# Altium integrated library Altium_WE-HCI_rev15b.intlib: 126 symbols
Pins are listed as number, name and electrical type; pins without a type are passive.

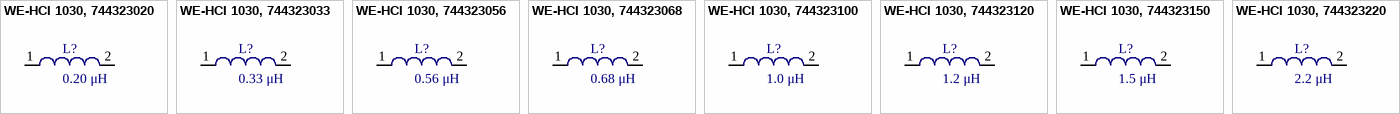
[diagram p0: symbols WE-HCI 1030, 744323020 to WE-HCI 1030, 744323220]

## WE-HCI 1030, 744323020
designator L?, comment 0.20 μH
WE-HCI SMD Flat Wire High Current Inductor, Inductance = 0.20 μH; partNo: 744323020; Manufacturer: Wurth Elektronik
footprint WE-HCI 1030
pins: 1, 2

## WE-HCI 1030, 744323033
designator L?, comment 0.33 μH
WE-HCI SMD Flat Wire High Current Inductor, Inductance = 0.33 μH; partNo: 744323033; Manufacturer: Wurth Elektronik
footprint WE-HCI 1030
pins: 1, 2

## WE-HCI 1030, 744323056
designator L?, comment 0.56 μH
WE-HCI SMD Flat Wire High Current Inductor, Inductance = 0.56 μH; partNo: 744323056; Manufacturer: Wurth Elektronik
footprint WE-HCI 1030
pins: 1, 2

## WE-HCI 1030, 744323068
designator L?, comment 0.68 μH
WE-HCI SMD Flat Wire High Current Inductor, Inductance = 0.68 μH; partNo: 744323068; Manufacturer: Wurth Elektronik
footprint WE-HCI 1030
pins: 1, 2

## WE-HCI 1030, 744323100
designator L?, comment 1.0 μH
WE-HCI SMD Flat Wire High Current Inductor, Inductance = 1.0 μH; partNo: 744323100; Manufacturer: Wurth Elektronik
footprint WE-HCI 1030
pins: 1, 2

## WE-HCI 1030, 744323120
designator L?, comment 1.2 μH
WE-HCI SMD Flat Wire High Current Inductor, Inductance = 1.2 μH; partNo: 744323120; Manufacturer: Wurth Elektronik
footprint WE-HCI 1030
pins: 1, 2

## WE-HCI 1030, 744323150
designator L?, comment 1.5 μH
WE-HCI SMD Flat Wire High Current Inductor, Inductance = 1.5 μH; partNo: 744323150; Manufacturer: Wurth Elektronik
footprint WE-HCI 1030
pins: 1, 2

## WE-HCI 1030, 744323220
designator L?, comment 2.2 μH
WE-HCI SMD Flat Wire High Current Inductor, Inductance = 2.2 μH; partNo: 744323220; Manufacturer: Wurth Elektronik
footprint WE-HCI 1030
pins: 1, 2


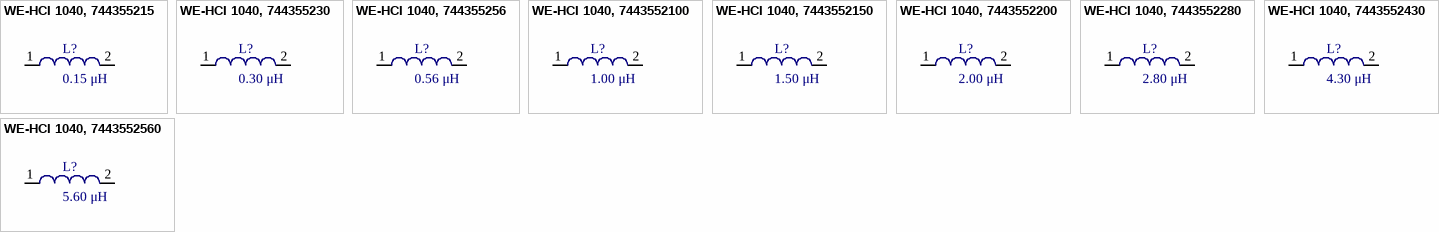
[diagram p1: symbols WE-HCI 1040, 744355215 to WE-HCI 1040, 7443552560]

## WE-HCI 1040, 744355215
designator L?, comment 0.15 μH
WE-HCI SMD Flat Wire High Current Inductor, Inductance = 0.15 μH; partNo: 744355215; Manufacturer: Wurth Elektronik
footprint WE-HCI 1040
pins: 1, 2

## WE-HCI 1040, 744355230
designator L?, comment 0.30 μH
WE-HCI SMD Flat Wire High Current Inductor, Inductance = 0.30 μH; partNo: 744355230; Manufacturer: Wurth Elektronik
footprint WE-HCI 1040
pins: 1, 2

## WE-HCI 1040, 744355256
designator L?, comment 0.56 μH
WE-HCI SMD Flat Wire High Current Inductor, Inductance = 0.56 μH; partNo: 744355256; Manufacturer: Wurth Elektronik
footprint WE-HCI 1040
pins: 1, 2

## WE-HCI 1040, 7443552100
designator L?, comment 1.00 μH
WE-HCI SMD Flat Wire High Current Inductor, Inductance = 1.00 μH; partNo: 7443552100; Manufacturer: Wurth Elektronik
footprint WE-HCI 1040
pins: 1, 2

## WE-HCI 1040, 7443552150
designator L?, comment 1.50 μH
WE-HCI SMD Flat Wire High Current Inductor, Inductance = 1.50 μH; partNo: 7443552150; Manufacturer: Wurth Elektronik
footprint WE-HCI 1040
pins: 1, 2

## WE-HCI 1040, 7443552200
designator L?, comment 2.00 μH
WE-HCI SMD Flat Wire High Current Inductor, Inductance = 2.00 μH; partNo: 7443552200; Manufacturer: Wurth Elektronik
footprint WE-HCI 1040
pins: 1, 2

## WE-HCI 1040, 7443552280
designator L?, comment 2.80 μH
WE-HCI SMD Flat Wire High Current Inductor, Inductance = 2.80 μH; partNo: 7443552280; Manufacturer: Wurth Elektronik
footprint WE-HCI 1040
pins: 1, 2

## WE-HCI 1040, 7443552430
designator L?, comment 4.30 μH
WE-HCI SMD Flat Wire High Current Inductor, Inductance = 4.30 μH; partNo: 7443552430; Manufacturer: Wurth Elektronik
footprint WE-HCI 1040
pins: 1, 2

## WE-HCI 1040, 7443552560
designator L?, comment 5.60 μH
WE-HCI SMD Flat Wire High Current Inductor, Inductance = 5.60 μH; partNo: 7443552560; Manufacturer: Wurth Elektronik
footprint WE-HCI 1040
pins: 1, 2


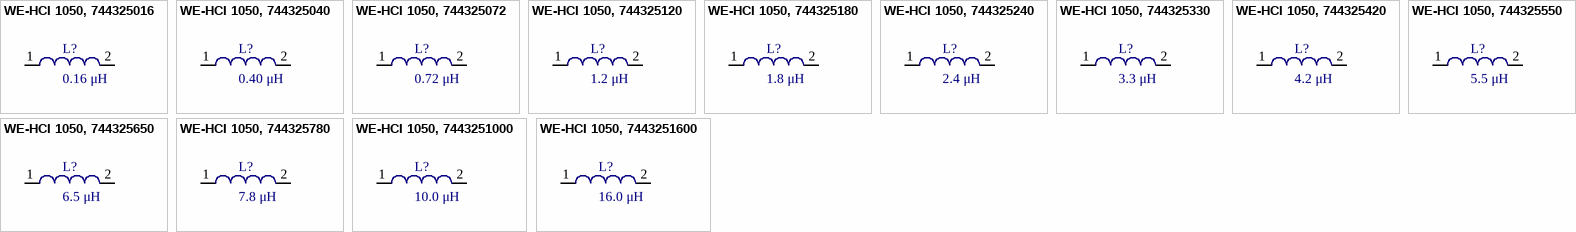
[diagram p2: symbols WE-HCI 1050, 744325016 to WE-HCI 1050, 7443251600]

## WE-HCI 1050, 744325016
designator L?, comment 0.16 μH
WE-HCI SMD Flat Wire High Current Inductor, Inductance = 0.16 μH; partNo: 744325016; Manufacturer: Wurth Elektronik
footprint WE-HCI 1050
pins: 1, 2

## WE-HCI 1050, 744325040
designator L?, comment 0.40 μH
WE-HCI SMD Flat Wire High Current Inductor, Inductance = 0.40 μH; partNo: 744325040; Manufacturer: Wurth Elektronik
footprint WE-HCI 5040
pins: 1, 2

## WE-HCI 1050, 744325072
designator L?, comment 0.72 μH
WE-HCI SMD Flat Wire High Current Inductor, Inductance = 0.72 μH; partNo: 744325072; Manufacturer: Wurth Elektronik
footprint WE-HCI 1050
pins: 1, 2

## WE-HCI 1050, 744325120
designator L?, comment 1.2 μH
WE-HCI SMD Flat Wire High Current Inductor, Inductance = 1.2 μH; partNo: 744325120; Manufacturer: Wurth Elektronik
footprint WE-HCI 1050
pins: 1, 2

## WE-HCI 1050, 744325180
designator L?, comment 1.8 μH
WE-HCI SMD Flat Wire High Current Inductor, Inductance = 1.8 μH; partNo: 744325180; Manufacturer: Wurth Elektronik
footprint WE-HCI 1050
pins: 1, 2

## WE-HCI 1050, 744325240
designator L?, comment 2.4 μH
WE-HCI SMD Flat Wire High Current Inductor, Inductance = 2.4 μH; partNo: 744325240; Manufacturer: Wurth Elektronik
footprint WE-HCI 1050
pins: 1, 2

## WE-HCI 1050, 744325330
designator L?, comment 3.3 μH
WE-HCI SMD Flat Wire High Current Inductor, Inductance = 3.3 μH; partNo: 744325330; Manufacturer: Wurth Elektronik
footprint WE-HCI 1050
pins: 1, 2

## WE-HCI 1050, 744325420
designator L?, comment 4.2 μH
WE-HCI SMD Flat Wire High Current Inductor, Inductance = 4.2 μH; partNo: 744325420; Manufacturer: Wurth Elektronik
footprint WE-HCI 1050
pins: 1, 2

## WE-HCI 1050, 744325550
designator L?, comment 5.5 μH
WE-HCI SMD Flat Wire High Current Inductor, Inductance = 5.5 μH; partNo: 744325550; Manufacturer: Wurth Elektronik
footprint WE-HCI 1050
pins: 1, 2

## WE-HCI 1050, 744325650
designator L?, comment 6.5 μH
WE-HCI SMD Flat Wire High Current Inductor, Inductance = 6.5 μH; partNo: 744325650; Manufacturer: Wurth Elektronik
footprint WE-HCI 1050
pins: 1, 2

## WE-HCI 1050, 744325780
designator L?, comment 7.8 μH
WE-HCI SMD Flat Wire High Current Inductor, Inductance = 7.8 μH; partNo: 744325780; Manufacturer: Wurth Elektronik
footprint WE-HCI 1050
pins: 1, 2

## WE-HCI 1050, 7443251000
designator L?, comment 10.0 μH
WE-HCI SMD Flat Wire High Current Inductor, Inductance = 10.0 μH; partNo: 7443251000; Manufacturer: Wurth Elektronik
footprint WE-HCI 1050
pins: 1, 2

## WE-HCI 1050, 7443251600
designator L?, comment 16.0 μH
WE-HCI SMD Flat Wire High Current Inductor, Inductance = 16.0 μH; partNo: 7443251600; Manufacturer: Wurth Elektronik
footprint WE-HCI 1050
pins: 1, 2


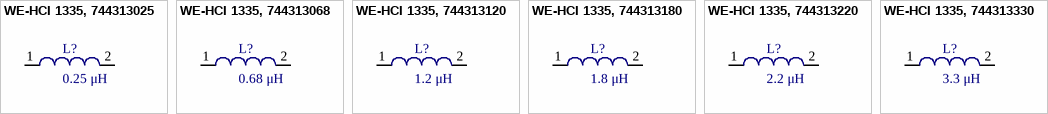
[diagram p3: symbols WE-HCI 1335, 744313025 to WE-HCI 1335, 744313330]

## WE-HCI 1335, 744313025
designator L?, comment 0.25 μH
WE-HCI SMD Flat Wire High Current Inductor, Inductance = 0.25 μH; partNo: 744313025; Manufacturer: Wurth Elektronik
footprint WE-HCI 1335
pins: 1, 2

## WE-HCI 1335, 744313068
designator L?, comment 0.68 μH
WE-HCI SMD Flat Wire High Current Inductor, Inductance = 0.68 μH; partNo: 744313068; Manufacturer: Wurth Elektronik
footprint WE-HCI 1335
pins: 1, 2

## WE-HCI 1335, 744313120
designator L?, comment 1.2 μH
WE-HCI SMD Flat Wire High Current Inductor, Inductance = 1.2 μH; partNo: 744313120; Manufacturer: Wurth Elektronik
footprint WE-HCI 1335
pins: 1, 2

## WE-HCI 1335, 744313180
designator L?, comment 1.8 μH
WE-HCI SMD Flat Wire High Current Inductor, Inductance = 1.8 μH; partNo: 744313180; Manufacturer: Wurth Elektronik
footprint WE-HCI 1335
pins: 1, 2

## WE-HCI 1335, 744313220
designator L?, comment 2.2 μH
WE-HCI SMD Flat Wire High Current Inductor, Inductance = 2.2 μH; partNo: 744313220; Manufacturer: Wurth Elektronik
footprint WE-HCI 1335
pins: 1, 2

## WE-HCI 1335, 744313330
designator L?, comment 3.3 μH
WE-HCI SMD Flat Wire High Current Inductor, Inductance = 3.3 μH; partNo: 744313330; Manufacturer: Wurth Elektronik
footprint WE-HCI 1335 (SMD Inductor, 2-Leads, Body 12,9x12,8mm)
pins: 1, 2


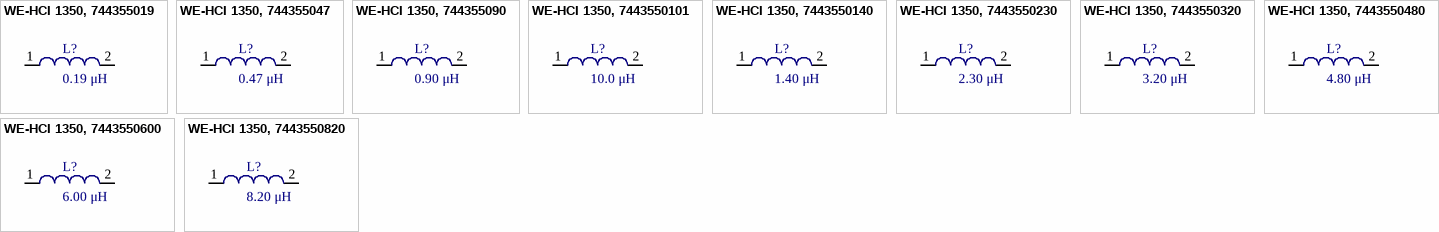
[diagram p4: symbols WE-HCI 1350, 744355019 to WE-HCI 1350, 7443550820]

## WE-HCI 1350, 744355019
designator L?, comment 0.19 μH
WE-HCI SMD Flat Wire High Current Inductor, Inductance = 0.19 μH; partNo: 744355019; Manufacturer: Wurth Elektronik
footprint WE-HCI 1350
pins: 1, 2

## WE-HCI 1350, 744355047
designator L?, comment 0.47 μH
WE-HCI SMD Flat Wire High Current Inductor, Inductance = 0.47 μH; partNo: 744355047; Manufacturer: Wurth Elektronik
footprint WE-HCI 1350
pins: 1, 2

## WE-HCI 1350, 744355090
designator L?, comment 0.90 μH
WE-HCI SMD Flat Wire High Current Inductor, Inductance = 0.90 μH; partNo: 744355090; Manufacturer: Wurth Elektronik
footprint WE-HCI 1350
pins: 1, 2

## WE-HCI 1350, 7443550101
designator L?, comment 10.0 μH
WE-HCI SMD Flat Wire High Current Inductor, Inductance = 10.0 μH; partNo: 7443550101; Manufacturer: Wurth Elektronik
footprint WE-HCI 1350
pins: 1, 2

## WE-HCI 1350, 7443550140
designator L?, comment 1.40 μH
WE-HCI SMD Flat Wire High Current Inductor, Inductance = 1.40 μH; partNo: 7443550140; Manufacturer: Wurth Elektronik
footprint WE-HCI 1350
pins: 1, 2

## WE-HCI 1350, 7443550230
designator L?, comment 2.30 μH
WE-HCI SMD Flat Wire High Current Inductor, Inductance = 2.30 μH; partNo: 7443550230; Manufacturer: Wurth Elektronik
footprint WE-HCI 1350
pins: 1, 2

## WE-HCI 1350, 7443550320
designator L?, comment 3.20 μH
WE-HCI SMD Flat Wire High Current Inductor, Inductance = 3.20 μH; partNo: 7443550320; Manufacturer: Wurth Elektronik
footprint WE-HCI 1350
pins: 1, 2

## WE-HCI 1350, 7443550480
designator L?, comment 4.80 μH
WE-HCI SMD Flat Wire High Current Inductor, Inductance = 4.80 μH; partNo: 7443550480; Manufacturer: Wurth Elektronik
footprint WE-HCI 1350
pins: 1, 2

## WE-HCI 1350, 7443550600
designator L?, comment 6.00 μH
WE-HCI SMD Flat Wire High Current Inductor, Inductance = 6.00 μH; partNo: 7443550600; Manufacturer: Wurth Elektronik
footprint WE-HCI 1350
pins: 1, 2

## WE-HCI 1350, 7443550820
designator L?, comment 8.20 μH
WE-HCI SMD Flat Wire High Current Inductor, Inductance = 8.20 μH; partNo: 7443550820; Manufacturer: Wurth Elektronik
footprint WE-HCI 1350
pins: 1, 2


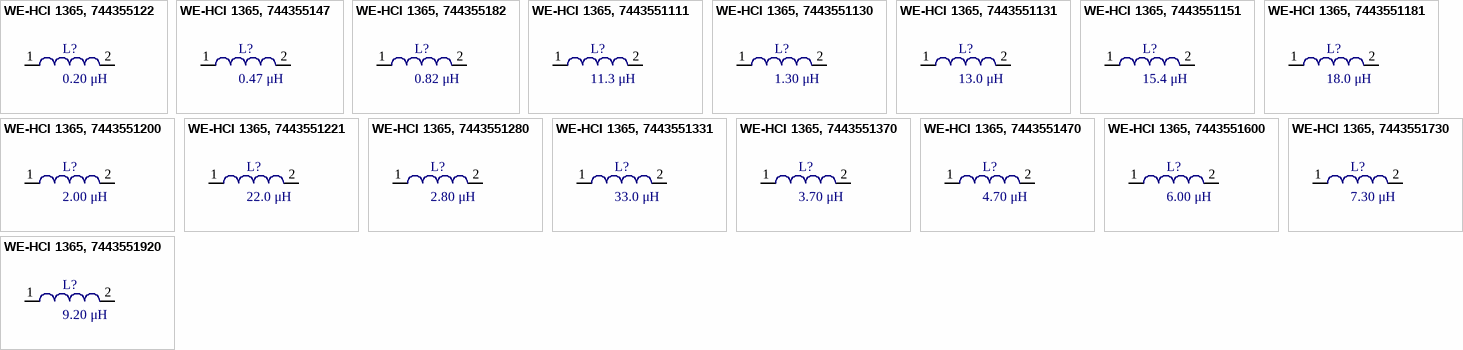
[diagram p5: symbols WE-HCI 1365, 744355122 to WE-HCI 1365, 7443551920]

## WE-HCI 1365, 744355122
designator L?, comment 0.20 μH
WE-HCI SMD Flat Wire High Current Inductor, Inductance = 0.20 μH; partNo: 744355122; Manufacturer: Wurth Elektronik
footprint WE-HCI 1365
pins: 1, 2

## WE-HCI 1365, 744355147
designator L?, comment 0.47 μH
WE-HCI SMD Flat Wire High Current Inductor, Inductance = 0.47 μH; partNo: 744355147; Manufacturer: Wurth Elektronik
footprint WE-HCI 1365
pins: 1, 2

## WE-HCI 1365, 744355182
designator L?, comment 0.82 μH
WE-HCI SMD Flat Wire High Current Inductor, Inductance = 0.82 μH; partNo: 744355182; Manufacturer: Wurth Elektronik
footprint WE-HCI 1365
pins: 1, 2

## WE-HCI 1365, 7443551111
designator L?, comment 11.3 μH
WE-HCI SMD Flat Wire High Current Inductor, Inductance = 11.3 μH; partNo: 7443551111; Manufacturer: Wurth Elektronik
footprint WE-HCI 1365
pins: 1, 2

## WE-HCI 1365, 7443551130
designator L?, comment 1.30 μH
WE-HCI SMD Flat Wire High Current Inductor, Inductance = 1.30 μH; partNo: 7443551130; Manufacturer: Wurth Elektronik
footprint WE-HCI 1365
pins: 1, 2

## WE-HCI 1365, 7443551131
designator L?, comment 13.0 μH
WE-HCI SMD Flat Wire High Current Inductor, Inductance = 13.0 μH; partNo: 7443551131; Manufacturer: Wurth Elektronik
footprint WE-HCI 1365
pins: 1, 2

## WE-HCI 1365, 7443551151
designator L?, comment 15.4 μH
WE-HCI SMD Flat Wire High Current Inductor, Inductance = 15.4 μH; partNo: 7443551151; Manufacturer: Wurth Elektronik
footprint WE-HCI 1365
pins: 1, 2

## WE-HCI 1365, 7443551181
designator L?, comment 18.0 μH
WE-HCI SMD Flat Wire High Current Inductor, Inductance = 18.0 μH; partNo: 7443551181; Manufacturer: Wurth Elektronik
footprint WE-HCI 1365
pins: 1, 2

## WE-HCI 1365, 7443551200
designator L?, comment 2.00 μH
WE-HCI SMD Flat Wire High Current Inductor, Inductance = 2.00 μH; partNo: 7443551200; Manufacturer: Wurth Elektronik
footprint WE-HCI 1365
pins: 1, 2

## WE-HCI 1365, 7443551221
designator L?, comment 22.0 μH
WE-HCI SMD Flat Wire High Current Inductor, Inductance = 22.0 μH; partNo: 7443551221; Manufacturer: Wurth Elektronik
footprint WE-HCI 1365
pins: 1, 2

## WE-HCI 1365, 7443551280
designator L?, comment 2.80 μH
WE-HCI SMD Flat Wire High Current Inductor, Inductance = 2.80 μH; partNo: 7443551280; Manufacturer: Wurth Elektronik
footprint WE-HCI 1365
pins: 1, 2

## WE-HCI 1365, 7443551331
designator L?, comment 33.0 μH
WE-HCI SMD Flat Wire High Current Inductor, Inductance = 33.0 μH; partNo: 7443551331; Manufacturer: Wurth Elektronik
footprint WE-HCI 1365
pins: 1, 2

## WE-HCI 1365, 7443551370
designator L?, comment 3.70 μH
WE-HCI SMD Flat Wire High Current Inductor, Inductance = 3.70 μH; partNo: 7443551370; Manufacturer: Wurth Elektronik
footprint WE-HCI 1365
pins: 1, 2

## WE-HCI 1365, 7443551470
designator L?, comment 4.70 μH
WE-HCI SMD Flat Wire High Current Inductor, Inductance = 4.70 μH; partNo: 7443551470; Manufacturer: Wurth Elektronik
footprint WE-HCI 1365
pins: 1, 2

## WE-HCI 1365, 7443551600
designator L?, comment 6.00 μH
WE-HCI SMD Flat Wire High Current Inductor, Inductance = 6.00 μH; partNo: 7443551600; Manufacturer: Wurth Elektronik
footprint WE-HCI 1365
pins: 1, 2

## WE-HCI 1365, 7443551730
designator L?, comment 7.30 μH
WE-HCI SMD Flat Wire High Current Inductor, Inductance = 7.30 μH; partNo: 7443551730; Manufacturer: Wurth Elektronik
footprint WE-HCI 1365
pins: 1, 2

## WE-HCI 1365, 7443551920
designator L?, comment 9.20 μH
WE-HCI SMD Flat Wire High Current Inductor, Inductance = 9.20 μH; partNo: 7443551920; Manufacturer: Wurth Elektronik
footprint WE-HCI 1365
pins: 1, 2


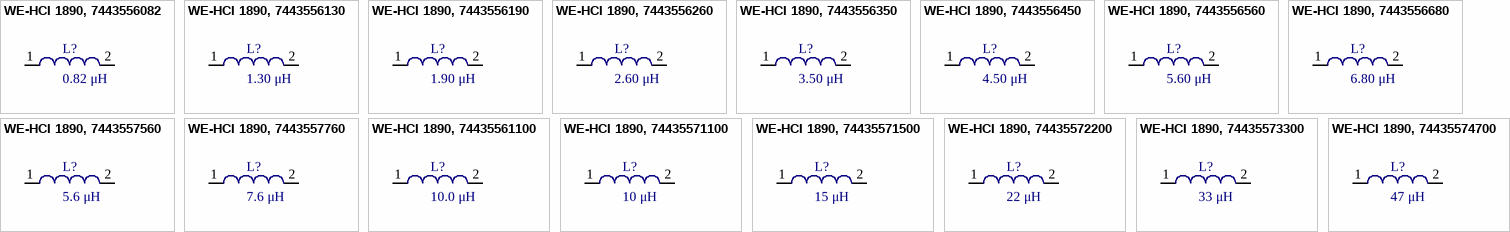
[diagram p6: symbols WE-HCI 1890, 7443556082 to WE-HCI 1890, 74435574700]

## WE-HCI 1890, 7443556082
designator L?, comment 0.82 μH
WE-HCI SMD Flat Wire High Current Inductor, Inductance = 0.82 μH; partNo: 7443556082; Manufacturer: Wurth Elektronik
footprint WE-HCI 1890_7443556x
pins: 1, 2

## WE-HCI 1890, 7443556130
designator L?, comment 1.30 μH
WE-HCI SMD Flat Wire High Current Inductor, Inductance = 1.30 μH; partNo: 7443556130; Manufacturer: Wurth Elektronik
footprint WE-HCI 1890_7443556x
pins: 1, 2

## WE-HCI 1890, 7443556190
designator L?, comment 1.90 μH
WE-HCI SMD Flat Wire High Current Inductor, Inductance = 1.90 μH; partNo: 7443556190; Manufacturer: Wurth Elektronik
footprint WE-HCI 1890_7443556x
pins: 1, 2

## WE-HCI 1890, 7443556260
designator L?, comment 2.60 μH
WE-HCI SMD Flat Wire High Current Inductor, Inductance = 2.60 μH; partNo: 7443556260; Manufacturer: Wurth Elektronik
footprint WE-HCI 1890_7443556x
pins: 1, 2

## WE-HCI 1890, 7443556350
designator L?, comment 3.50 μH
WE-HCI SMD Flat Wire High Current Inductor, Inductance = 3.50 μH; partNo: 7443556350; Manufacturer: Wurth Elektronik
footprint WE-HCI 1890_7443556x
pins: 1, 2

## WE-HCI 1890, 7443556450
designator L?, comment 4.50 μH
WE-HCI SMD Flat Wire High Current Inductor, Inductance = 4.50 μH; partNo: 7443556450; Manufacturer: Wurth Elektronik
footprint WE-HCI 1890_7443556x
pins: 1, 2

## WE-HCI 1890, 7443556560
designator L?, comment 5.60 μH
WE-HCI SMD Flat Wire High Current Inductor, Inductance = 5.60 μH; partNo: 7443556560; Manufacturer: Wurth Elektronik
footprint WE-HCI 1890_7443556x
pins: 1, 2

## WE-HCI 1890, 7443556680
designator L?, comment 6.80 μH
WE-HCI SMD Flat Wire High Current Inductor, Inductance = 6.80 μH; partNo: 7443556680; Manufacturer: Wurth Elektronik
footprint WE-HCI 1890_7443556x
pins: 1, 2

## WE-HCI 1890, 7443557560
designator L?, comment 5.6 μH
WE-HCI SMD Flat Wire High Current Inductor, Inductance = 5.6 μH; partNo: 7443557560; Manufacturer: Wurth Elektronik
footprint WE-HCI 1890_7443557x
pins: 1, 2

## WE-HCI 1890, 7443557760
designator L?, comment 7.6 μH
WE-HCI SMD Flat Wire High Current Inductor, Inductance = 7.6 μH; partNo: 7443557760; Manufacturer: Wurth Elektronik
footprint WE-HCI 1890_7443557x
pins: 1, 2

## WE-HCI 1890, 74435561100
designator L?, comment 10.0 μH
WE-HCI SMD Flat Wire High Current Inductor, Inductance = 10.0 μH; partNo: 74435561100; Manufacturer: Wurth Elektronik
footprint WE-HCI 1890_7443556x
pins: 1, 2

## WE-HCI 1890, 74435571100
designator L?, comment 10 μH
WE-HCI SMD Flat Wire High Current Inductor, Inductance = 10 μH; partNo: 74435571100; Manufacturer: Wurth Elektronik
footprint WE-HCI 1890_7443557x
pins: 1, 2

## WE-HCI 1890, 74435571500
designator L?, comment 15 μH
WE-HCI SMD Flat Wire High Current Inductor, Inductance = 15 μH; partNo: 74435571500; Manufacturer: Wurth Elektronik
footprint WE-HCI 1890_7443557x
pins: 1, 2

## WE-HCI 1890, 74435572200
designator L?, comment 22 μH
WE-HCI SMD Flat Wire High Current Inductor, Inductance = 22 μH; partNo: 74435572200; Manufacturer: Wurth Elektronik
footprint WE-HCI 1890_7443557x
pins: 1, 2

## WE-HCI 1890, 74435573300
designator L?, comment 33 μH
WE-HCI SMD Flat Wire High Current Inductor, Inductance = 33 μH; partNo: 74435573300; Manufacturer: Wurth Elektronik
footprint WE-HCI 1890_7443557x
pins: 1, 2

## WE-HCI 1890, 74435574700
designator L?, comment 47 μH
WE-HCI SMD Flat Wire High Current Inductor, Inductance = 47 μH; partNo: 74435574700; Manufacturer: Wurth Elektronik
footprint WE-HCI 1890_7443557x
pins: 1, 2


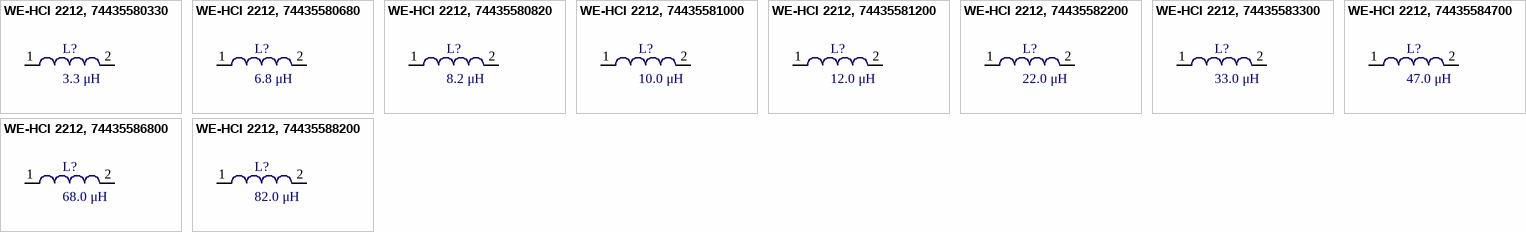
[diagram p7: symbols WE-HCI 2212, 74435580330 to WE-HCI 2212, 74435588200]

## WE-HCI 2212, 74435580330
designator L?, comment 3.3 μH
WE-HCI SMD Flat Wire High Current Inductor, Inductance = 3.3 μH; partNo: 74435580330; Manufacturer: Wurth Elektronik
footprint WE-HCI 2212
pins: 1, 2

## WE-HCI 2212, 74435580680
designator L?, comment 6.8 μH
WE-HCI SMD Flat Wire High Current Inductor, Inductance = 6.8 μH; partNo: 74435580680; Manufacturer: Wurth Elektronik
footprint WE-HCI 2212
pins: 1, 2

## WE-HCI 2212, 74435580820
designator L?, comment 8.2 μH
WE-HCI SMD Flat Wire High Current Inductor, Inductance = 8.2 μH; partNo: 74435580820; Manufacturer: Wurth Elektronik
footprint WE-HCI 2212
pins: 1, 2

## WE-HCI 2212, 74435581000
designator L?, comment 10.0 μH
WE-HCI SMD Flat Wire High Current Inductor, Inductance = 10.0 μH; partNo: 74435581000; Manufacturer: Wurth Elektronik
footprint WE-HCI 2212
pins: 1, 2

## WE-HCI 2212, 74435581200
designator L?, comment 12.0 μH
WE-HCI SMD Flat Wire High Current Inductor, Inductance = 12.0 μH; partNo: 74435581200; Manufacturer: Wurth Elektronik
footprint WE-HCI 2212
pins: 1, 2

## WE-HCI 2212, 74435582200
designator L?, comment 22.0 μH
WE-HCI SMD Flat Wire High Current Inductor, Inductance = 22.0 μH; partNo: 74435582200; Manufacturer: Wurth Elektronik
footprint WE-HCI 2212
pins: 1, 2

## WE-HCI 2212, 74435583300
designator L?, comment 33.0 μH
WE-HCI SMD Flat Wire High Current Inductor, Inductance = 33.0 μH; partNo: 74435583300; Manufacturer: Wurth Elektronik
footprint WE-HCI 2212
pins: 1, 2

## WE-HCI 2212, 74435584700
designator L?, comment 47.0 μH
WE-HCI SMD Flat Wire High Current Inductor, Inductance = 47.0 μH; partNo: 74435584700; Manufacturer: Wurth Elektronik
footprint WE-HCI 2212
pins: 1, 2

## WE-HCI 2212, 74435586800
designator L?, comment 68.0 μH
WE-HCI SMD Flat Wire High Current Inductor, Inductance = 68.0 μH; partNo: 74435586800; Manufacturer: Wurth Elektronik
footprint WE-HCI 2212
pins: 1, 2

## WE-HCI 2212, 74435588200
designator L?, comment 82.0 μH
WE-HCI SMD Flat Wire High Current Inductor, Inductance = 82.0 μH; partNo: 74435588200; Manufacturer: Wurth Elektronik
footprint WE-HCI 2212
pins: 1, 2


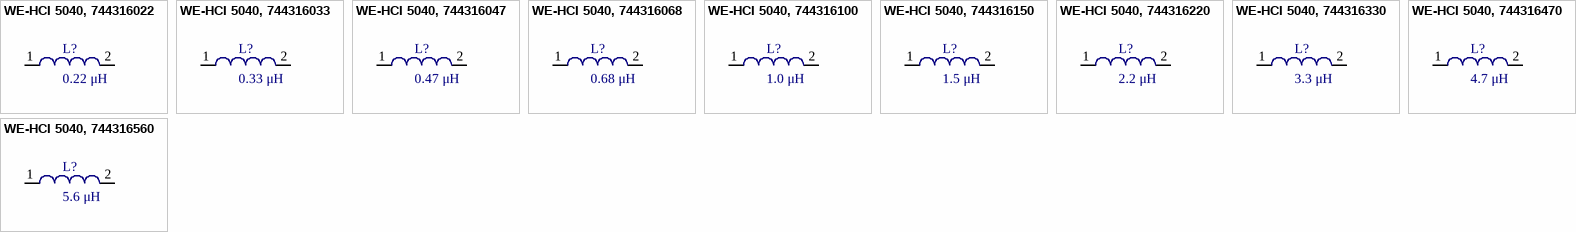
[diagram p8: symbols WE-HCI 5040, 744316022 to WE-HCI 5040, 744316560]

## WE-HCI 5040, 744316022
designator L?, comment 0.22 μH
WE-HCI SMD Flat Wire High Current Inductor, Inductance = 0.22 μH; partNo: 744316022; Manufacturer: Wurth Elektronik
footprint WE-HCI 5040
pins: 1, 2

## WE-HCI 5040, 744316033
designator L?, comment 0.33 μH
WE-HCI SMD Flat Wire High Current Inductor, Inductance = 0.33 μH; partNo: 744316033; Manufacturer: Wurth Elektronik
footprint WE-HCI 5040
pins: 1, 2

## WE-HCI 5040, 744316047
designator L?, comment 0.47 μH
WE-HCI SMD Flat Wire High Current Inductor, Inductance = 0.47 μH; partNo: 744316047; Manufacturer: Wurth Elektronik
footprint WE-HCI 5040
pins: 1, 2

## WE-HCI 5040, 744316068
designator L?, comment 0.68 μH
WE-HCI SMD Flat Wire High Current Inductor, Inductance = 0.68 μH; partNo: 744316068; Manufacturer: Wurth Elektronik
footprint WE-HCI 5040
pins: 1, 2

## WE-HCI 5040, 744316100
designator L?, comment 1.0 μH
WE-HCI SMD Flat Wire High Current Inductor, Inductance = 1.0 μH; partNo: 744316100; Manufacturer: Wurth Elektronik
footprint WE-HCI 5040
pins: 1, 2

## WE-HCI 5040, 744316150
designator L?, comment 1.5 μH
WE-HCI SMD Flat Wire High Current Inductor, Inductance = 1.5 μH; partNo: 744316150; Manufacturer: Wurth Elektronik
footprint WE-HCI 5040
pins: 1, 2

## WE-HCI 5040, 744316220
designator L?, comment 2.2 μH
WE-HCI SMD Flat Wire High Current Inductor, Inductance = 2.2 μH; partNo: 744316220; Manufacturer: Wurth Elektronik
footprint WE-HCI 5040
pins: 1, 2

## WE-HCI 5040, 744316330
designator L?, comment 3.3 μH
WE-HCI SMD Flat Wire High Current Inductor, Inductance = 3.3 μH; partNo: 744316330; Manufacturer: Wurth Elektronik
footprint WE-HCI 5040
pins: 1, 2

## WE-HCI 5040, 744316470
designator L?, comment 4.7 μH
WE-HCI SMD Flat Wire High Current Inductor, Inductance = 4.7 μH; partNo: 744316470; Manufacturer: Wurth Elektronik
footprint WE-HCI 5040
pins: 1, 2

## WE-HCI 5040, 744316560
designator L?, comment 5.6 μH
WE-HCI SMD Flat Wire High Current Inductor, Inductance = 5.6 μH; partNo: 744316560; Manufacturer: Wurth Elektronik
footprint WE-HCI 5040
pins: 1, 2


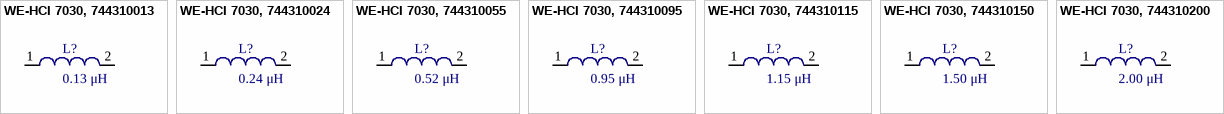
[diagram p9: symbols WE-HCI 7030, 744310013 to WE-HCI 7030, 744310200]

## WE-HCI 7030, 744310013
designator L?, comment 0.13 μH
WE-HCI SMD Flat Wire High Current Inductor, Inductance = 0.13 μH; partNo: 744310013; Manufacturer: Wurth Elektronik
footprint WE-HCI 7030
pins: 1, 2

## WE-HCI 7030, 744310024
designator L?, comment 0.24 μH
WE-HCI SMD Flat Wire High Current Inductor, Inductance = 0.24 μH; partNo: 744310024; Manufacturer: Wurth Elektronik
footprint WE-HCI 7030
pins: 1, 2

## WE-HCI 7030, 744310055
designator L?, comment 0.52 μH
WE-HCI SMD Flat Wire High Current Inductor, Inductance = 0.52 μH; partNo: 744310055; Manufacturer: Wurth Elektronik
footprint WE-HCI 7030
pins: 1, 2

## WE-HCI 7030, 744310095
designator L?, comment 0.95 μH
WE-HCI SMD Flat Wire High Current Inductor, Inductance = 0.95 μH; partNo: 744310095; Manufacturer: Wurth Elektronik
footprint WE-HCI 7030
pins: 1, 2

## WE-HCI 7030, 744310115
designator L?, comment 1.15 μH
WE-HCI SMD Flat Wire High Current Inductor, Inductance = 1.15 μH; partNo: 744310115; Manufacturer: Wurth Elektronik
footprint WE-HCI 7030
pins: 1, 2

## WE-HCI 7030, 744310150
designator L?, comment 1.50 μH
WE-HCI SMD Flat Wire High Current Inductor, Inductance = 1.50 μH; partNo: 744310150; Manufacturer: Wurth Elektronik
footprint WE-HCI 7030
pins: 1, 2

## WE-HCI 7030, 744310200
designator L?, comment 2.00 μH
WE-HCI SMD Flat Wire High Current Inductor, Inductance = 2.00 μH; partNo: 744310200; Manufacturer: Wurth Elektronik
footprint WE-HCI 7030
pins: 1, 2


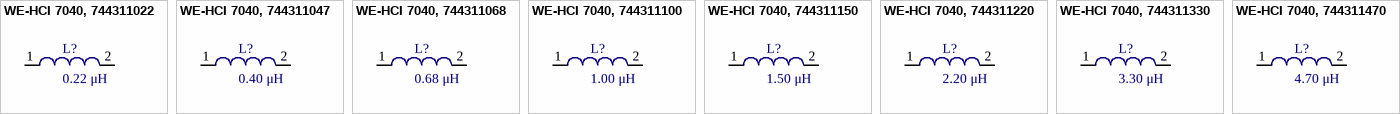
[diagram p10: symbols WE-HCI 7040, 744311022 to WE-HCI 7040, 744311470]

## WE-HCI 7040, 744311022
designator L?, comment 0.22 μH
WE-HCI SMD Flat Wire High Current Inductor, Inductance = 0.22 μH; partNo: 744311022; Manufacturer: Wurth Elektronik
footprint WE-HCI 7040
pins: 1, 2

## WE-HCI 7040, 744311047
designator L?, comment 0.40 μH
WE-HCI SMD Flat Wire High Current Inductor, Inductance = 0.40 μH; partNo: 744311047; Manufacturer: Wurth Elektronik
footprint WE-HCI 7040
pins: 1, 2

## WE-HCI 7040, 744311068
designator L?, comment 0.68 μH
WE-HCI SMD Flat Wire High Current Inductor, Inductance = 0.68 μH; partNo: 744311068; Manufacturer: Wurth Elektronik
footprint WE-HCI 7040
pins: 1, 2

## WE-HCI 7040, 744311100
designator L?, comment 1.00 μH
WE-HCI SMD Flat Wire High Current Inductor, Inductance = 1.00 μH; partNo: 744311100; Manufacturer: Wurth Elektronik
footprint WE-HCI 7040
pins: 1, 2

## WE-HCI 7040, 744311150
designator L?, comment 1.50 μH
WE-HCI SMD Flat Wire High Current Inductor, Inductance = 1.50 μH; partNo: 744311150; Manufacturer: Wurth Elektronik
footprint WE-HCI 7040
pins: 1, 2

## WE-HCI 7040, 744311220
designator L?, comment 2.20 μH
WE-HCI SMD Flat Wire High Current Inductor, Inductance = 2.20 μH; partNo: 744311220; Manufacturer: Wurth Elektronik
footprint WE-HCI 7040
pins: 1, 2

## WE-HCI 7040, 744311330
designator L?, comment 3.30 μH
WE-HCI SMD Flat Wire High Current Inductor, Inductance = 3.30 μH; partNo: 744311330; Manufacturer: Wurth Elektronik
footprint WE-HCI 7040
pins: 1, 2

## WE-HCI 7040, 744311470
designator L?, comment 4.70 μH
WE-HCI SMD Flat Wire High Current Inductor, Inductance = 4.70 μH; partNo: 744311470; Manufacturer: Wurth Elektronik
footprint WE-HCI 7040
pins: 1, 2


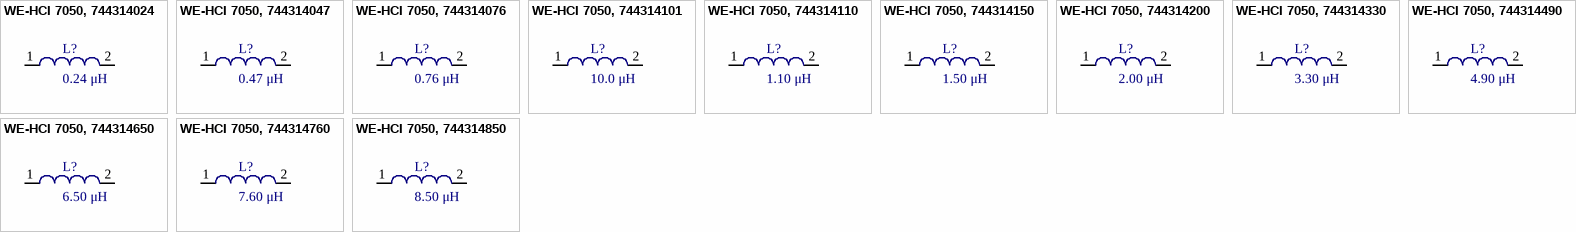
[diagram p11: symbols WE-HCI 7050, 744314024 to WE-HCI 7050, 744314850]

## WE-HCI 7050, 744314024
designator L?, comment 0.24 μH
WE-HCI SMD Flat Wire High Current Inductor, Inductance = 0.24 μH; partNo: 744314024; Manufacturer: Wurth Elektronik
footprint WE-HCI 7050
pins: 1, 2

## WE-HCI 7050, 744314047
designator L?, comment 0.47 μH
WE-HCI SMD Flat Wire High Current Inductor, Inductance = 0.47 μH; partNo: 744314047; Manufacturer: Wurth Elektronik
footprint WE-HCI 7050
pins: 1, 2

## WE-HCI 7050, 744314076
designator L?, comment 0.76 μH
WE-HCI SMD Flat Wire High Current Inductor, Inductance = 0.76 μH; partNo: 744314076; Manufacturer: Wurth Elektronik
footprint WE-HCI 7050
pins: 1, 2

## WE-HCI 7050, 744314101
designator L?, comment 10.0 μH
WE-HCI SMD Flat Wire High Current Inductor, Inductance = 10.0 μH; partNo: 744314101; Manufacturer: Wurth Elektronik
footprint WE-HCI 7050
pins: 1, 2

## WE-HCI 7050, 744314110
designator L?, comment 1.10 μH
WE-HCI SMD Flat Wire High Current Inductor, Inductance = 1.10 μH; partNo: 744314110; Manufacturer: Wurth Elektronik
footprint WE-HCI 7050
pins: 1, 2

## WE-HCI 7050, 744314150
designator L?, comment 1.50 μH
WE-HCI SMD Flat Wire High Current Inductor, Inductance = 1.50 μH; partNo: 744314150; Manufacturer: Wurth Elektronik
footprint WE-HCI 7050
pins: 1, 2

## WE-HCI 7050, 744314200
designator L?, comment 2.00 μH
WE-HCI SMD Flat Wire High Current Inductor, Inductance = 2.00 μH; partNo: 744314200; Manufacturer: Wurth Elektronik
footprint WE-HCI 7050
pins: 1, 2

## WE-HCI 7050, 744314330
designator L?, comment 3.30 μH
WE-HCI SMD Flat Wire High Current Inductor, Inductance = 3.30 μH; partNo: 744314330; Manufacturer: Wurth Elektronik
footprint WE-HCI 7050
pins: 1, 2

## WE-HCI 7050, 744314490
designator L?, comment 4.90 μH
WE-HCI SMD Flat Wire High Current Inductor, Inductance = 4.90 μH; partNo: 744314490; Manufacturer: Wurth Elektronik
footprint WE-HCI 7050
pins: 1, 2

## WE-HCI 7050, 744314650
designator L?, comment 6.50 μH
WE-HCI SMD Flat Wire High Current Inductor, Inductance = 6.50 μH; partNo: 744314650; Manufacturer: Wurth Elektronik
footprint WE-HCI 7050
pins: 1, 2

## WE-HCI 7050, 744314760
designator L?, comment 7.60 μH
WE-HCI SMD Flat Wire High Current Inductor, Inductance = 7.60 μH; partNo: 744314760; Manufacturer: Wurth Elektronik
footprint WE-HCI 7050
pins: 1, 2

## WE-HCI 7050, 744314850
designator L?, comment 8.50 μH
WE-HCI SMD Flat Wire High Current Inductor, Inductance = 8.50 μH; partNo: 744314850; Manufacturer: Wurth Elektronik
footprint WE-HCI 7050
pins: 1, 2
